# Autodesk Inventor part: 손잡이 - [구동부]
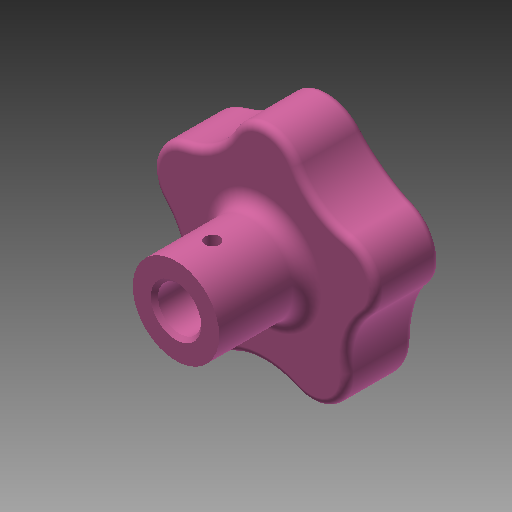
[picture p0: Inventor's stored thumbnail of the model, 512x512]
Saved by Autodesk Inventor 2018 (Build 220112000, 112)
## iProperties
Created: 2020-03
Part Number: 손잡이 - [구동부]
Material: 알루미늄 6061
Document SubType Name: Modeling
Designer: mduedu
Density: 2.71 g/cm^3
Appearance: 분홍색
Mass: 19.368 g
Surface Area: 28.5063 cm^2
Volume: 7.14686 cm^3
Author: mduedu
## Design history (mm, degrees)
sketch "스케치1" dims "d1" = 22
  geometry: C1 r 16 at (0, 0); C2 r 5 at (0, 11); C3 r 5 at (-10.462, 3.399); C4 r 5 at (-6.466, -8.899); C5 r 5 at (6.466, -8.899); C6 r 5 at (10.462, 3.399); 2 further points
  constraints: 6 centre point, 2 coincident, 2 vertical alignment, 1 tangent, 13 other
  dimensions: "d0" = 32 diameter of C1; "d4" = 360 deg dimension on point (0, 0) C2.centre (derived); "d6" = 10 diameter of C2 (derived)
extrude "돌출1" new body sketch "스케치1" distance "d8" = 10; taper "d9" = 0 deg
fillet "모깎기1" dims "d10" = 10
fillet "모깎기2" dims "d11" = 10
fillet "모깎기3" dims "d12" = 10
fillet "모깎기4" dims "d13" = 10
fillet "모깎기5" dims "d14" = 10
sketch "스케치2"
  geometry: L1 (16, 10)-(16, 0) reference; L2 (16, 0)-(-12.434, 0) reference; L3 (-12.434, 0)-(-12.434, 10) reference; L4 (-12.434, 10)-(16, 10) reference; L5 (10.5, 0)-(16, 1.169); L6 (16, 1.169)-(16, 0); L7 (16, 0)-(10.5, 0); L8 (0, 0)-(0, 10)
  constraints: 8 end point, 3 perpendicular, 3 point on line
  dimensions: "d15" = 5.5 distance of L5.start L1.end; "d16" = 12 deg angle of L2 L5
revolve "회전1" sketch "스케치2" stored, may be unused: angle "d17" = 90 deg
fillet "모깎기6" dims "d18" = 1
sketch "스케치3"
  geometry: C1 r 6 at (0, 0); 1 further point
  constraints: 1 centre point, 1 coincident
  dimensions: "d19" = 12 diameter of C1
extrude "돌출2" join sketch "스케치3" distance "d20" = 12.2; taper "d21" = 0 deg
fillet "모깎기7" dims "d22" = 2
hole "구멍1" diameter "d25" = 6; stored, may be unused: countersink angle "d29" = 90 deg, drill point angle "d31" = 118 deg; dims "d23" = 10, "d24" = 10, "d26" = 6, "d27" = 4, "d28" = 2, "d30" = 15
sketch "스케치4"
  geometry: L1 (6, 22.2)-(-6, 22.2) reference; C1 r 1 at (0, 17.2); 1 further point
  constraints: 1 centre point, 1 vertical alignment
  dimensions: "d32" = 2 diameter of C1; "d34" = 5 distance from line of C1.centre L1
extrude "돌출3" cut sketch "스케치4" extent not by distance; stored distance "d35" = 12.2; taper "d36" = 0 deg
chamfer "모따기2" distance "d40" = 0.5; stored, may be unused: second distance "d41" = 2, angle "d42" = 45 deg
node "솔리드1"
node "절단 모서리 투영1"
